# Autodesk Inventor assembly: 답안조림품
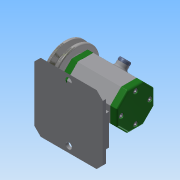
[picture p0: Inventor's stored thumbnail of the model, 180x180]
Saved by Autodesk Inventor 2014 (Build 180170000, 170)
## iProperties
Created: 2018-06
Part Number: 답안조림품
Document SubType Name: Assembly
Designer: net
Author: net
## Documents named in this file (16)
- C:\Users\net\Desktop\480607V1019\답안조림품.iam
- C:\Users\net\Desktop\480607V1019\본체.ipt
- C:\Users\net\Desktop\480607V1019\축.ipt
- C:\Users\net\Desktop\480607V1019\뒤커버.ipt
- C:\Users\net\Desktop\480607V1019\앞커버.ipt
- C:\Users\net\Desktop\480607V1019\키 3x3x12.ipt
- 키 3x3x12.ipt
- C:\Users\net\Desktop\480607V1019\V벨트풀리.ipt
- C:\Users\net\Desktop\480607V1019\고무캡.ipt
- C:\Users\net\Desktop\480607V1019\베어링 15x32x9.ipt
- C:\Users\net\Desktop\480607V1019\볼트 M4x12.ipt
- C:\Users\net\Desktop\480607V1019\스프링와셔 8.ipt
- C:\Users\net\Desktop\480607V1019\오일 실 15 25 7.ipt
- C:\Users\net\Desktop\480607V1019\와셔 8x17.ipt
- C:\Users\net\Desktop\480607V1019\너트 M8.ipt
- 너트 M8.ipt
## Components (2 placed, 2 different names)
1. V벨트풀리:1
2. 고무캡:1
